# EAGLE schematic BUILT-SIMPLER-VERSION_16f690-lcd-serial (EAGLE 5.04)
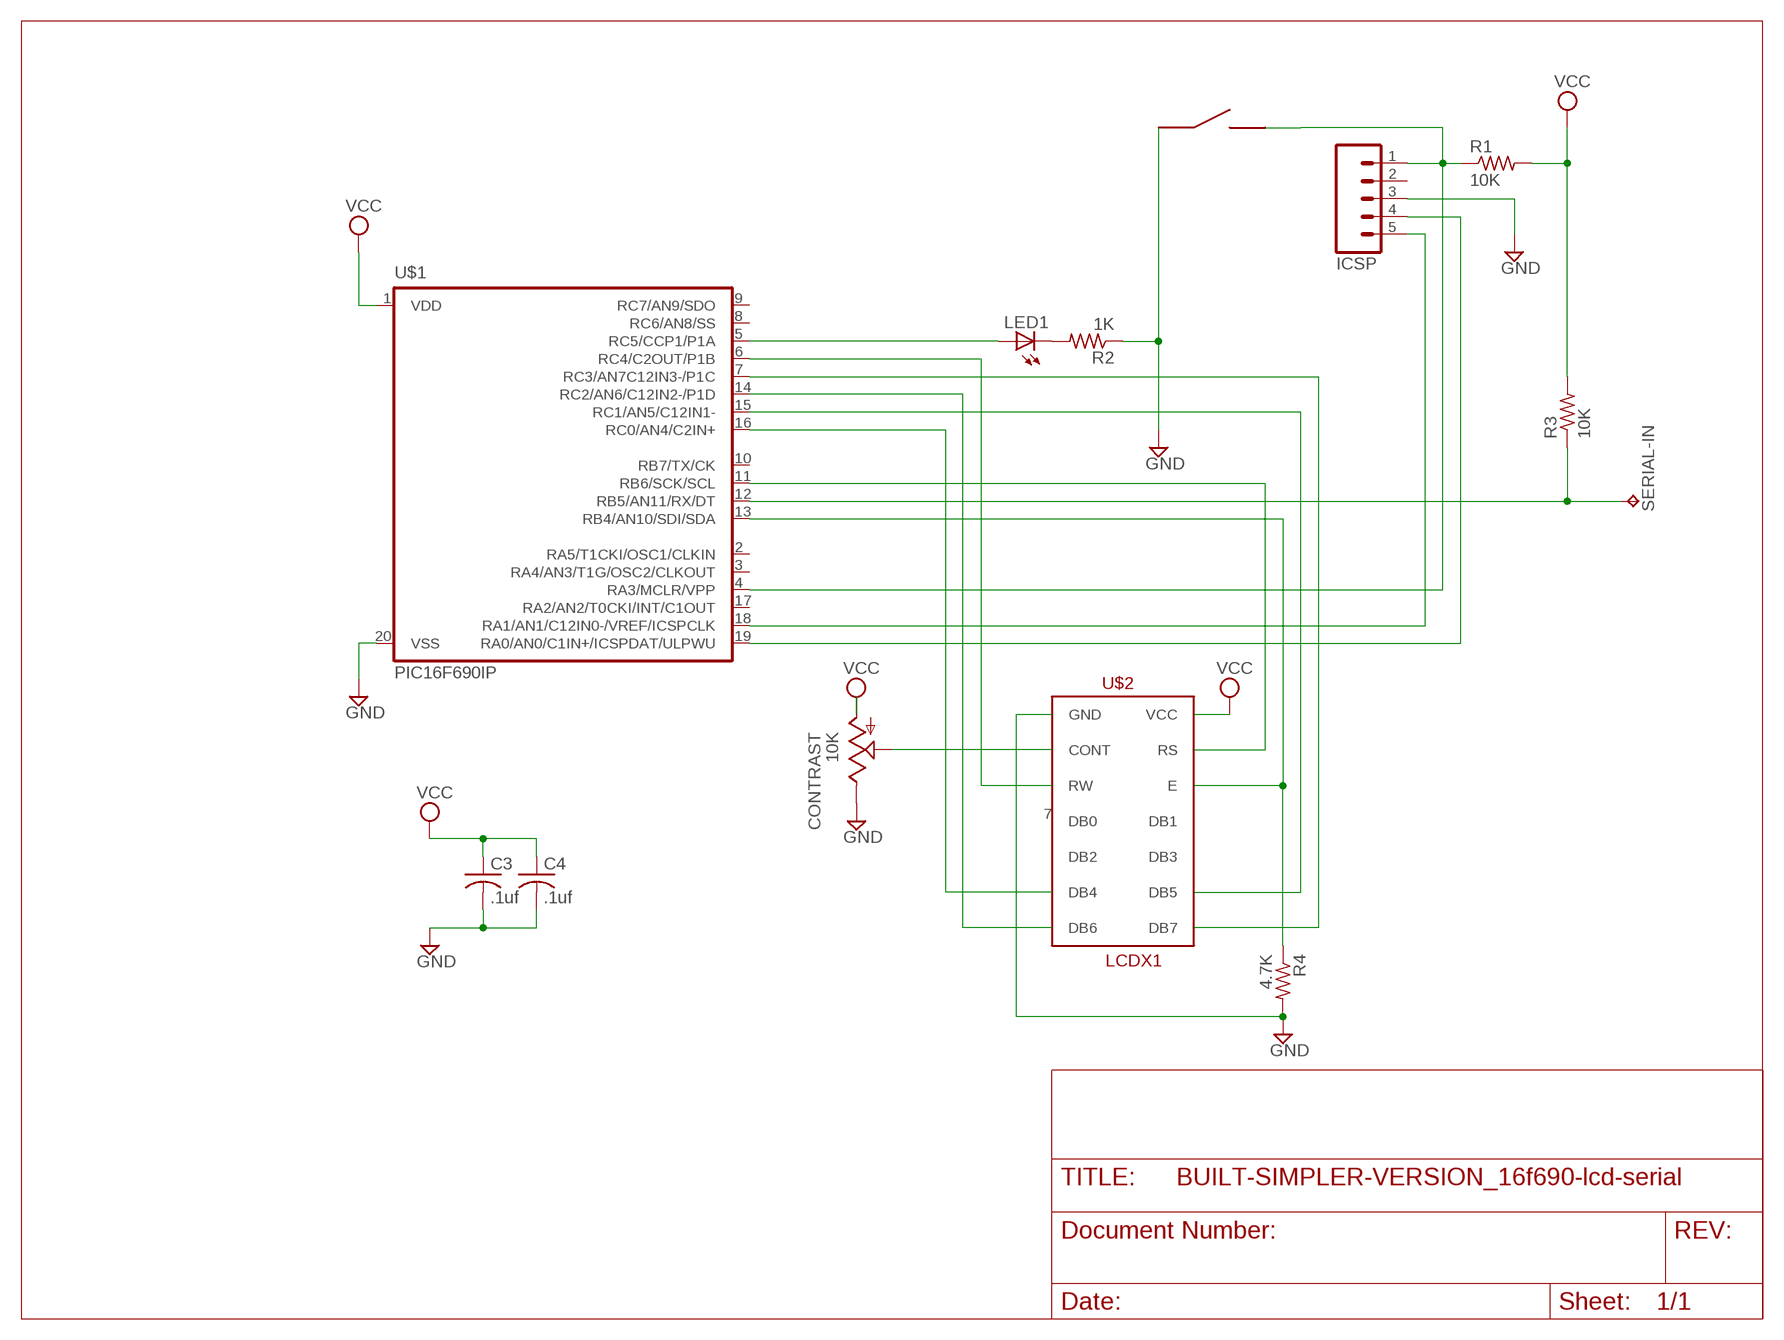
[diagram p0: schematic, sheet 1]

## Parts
C3  .1uf  C-US102-043X133  [C102-043X133]
C4  .1uf  C-US102-043X133  [C102-043X133]
CONTRAST  10K  TRIM_US-ECP10P  [ECP10P]
ICSP  M05  [05P]
LED1  LED5MM  [LED5MM]
R1  10K  R-US_0617/22  [0617/22]
R2  1K  R-US_0617/22  [0617/22]
R3  10K  R-US_0617/22  [0617/22]
R4  4.7K  R-US_0617/22  [0617/22]
RESET  PUSH-BUTTON-SWITCH  [2SIL]
SERIAL-IN  TPTP19R  [TP19R]
U$1  PIC16F690IP  [DIL20]
U$2  LCDX1  [7X2]

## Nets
GND: C3.2 C4.2 CONTRAST.E ICSP.3 R2.1 R4.2 RESET.NO U$1.20(VSS) U$2.1(GND)
N$1: ICSP.5 U$1.18(RA1/AN1/C12IN0-/VREF/ICSPCLK)
N$2: R3.1 SERIAL-IN.TP U$1.12(RB5/AN11/RX/DT)
N$3: LED1.K(C) R2.2
N$4: LED1.A U$1.5(RC5/CCP1/P1A)
N$5: R4.1 U$1.13(RB4/AN10/SDI/SDA) U$2.6(E)
N$6: U$1.6(RC4/C2OUT/P1B) U$2.5(RW)
N$7: U$1.11(RB6/SCK/SCL) U$2.4(RS)
N$8: U$1.16(RC0/AN4/C2IN+) U$2.11(DB4)
N$9: CONTRAST.S U$2.3(CONT)
N$10: U$1.7(RC3/AN7C12IN3-/P1C) U$2.14(DB7)
N$11: U$1.14(RC2/AN6/C12IN2-/P1D) U$2.13(DB6)
N$12: RESET.COM
N$13: U$1.15(RC1/AN5/C12IN1-) U$2.12(DB5)
N$15: ICSP.1 R1.1 U$1.4(RA3/MCLR/VPP)
N$16: ICSP.4 U$1.19(RA0/AN0/C1IN+/ICSPDAT/ULPWU)
VCC: C3.1 C4.1 CONTRAST.A R1.2 R3.2 U$1.1(VDD) U$2.2(VCC)
Unconnected: ICSP.2 U$1.2(RA5/T1CKI/OSC1/CLKIN) U$1.3(RA4/AN3/T1G/OSC2/CLKOUT) U$1.8(RC6/AN8/SS) U$1.9(RC7/AN9/SDO) U$1.10(RB7/TX/CK) U$1.17(RA2/AN2/T0CKI/INT/C1OUT) U$2.7(DB0) U$2.8(DB1) U$2.9(DB2) U$2.10(DB3)

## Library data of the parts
C3 C4 = rcl:C-US: CAPACITOR, American symbol
CONTRAST = pot:TRIM_US-: POTENTIOMETER
ICSP = con-amp-quick:M05: AMP QUICK CONNECTOR
LED1 = led:LED: LED
R1-R4 = resistor:R-US_: RESISTOR, American symbol
RESET = trl:PUSH-BUTTON-SWITCH
SERIAL-IN = testpad:TP: Test pad
U$1 = microchip-5:PIC16F690*: MICROCONTROLLER PIC16F690 18 I/O One 16-bit timer Two 8-bit timer Two comparators Precision internal oscillator-software selectable 8 MHz - 32 KHz SSP w/ I2C Compatible Address mask option EUSART LIN 2.0 Compatible ECCP+ w/ PWM Steering 12 A/D Channels ULPW Enhanced Low Power Timer 1 Timer 1 Gate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
U$2 = trl:LCDX1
